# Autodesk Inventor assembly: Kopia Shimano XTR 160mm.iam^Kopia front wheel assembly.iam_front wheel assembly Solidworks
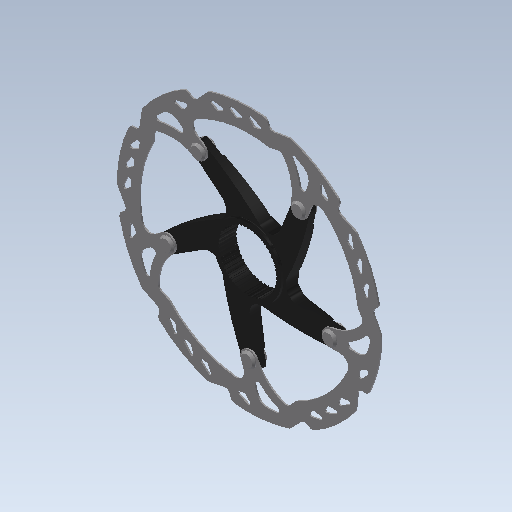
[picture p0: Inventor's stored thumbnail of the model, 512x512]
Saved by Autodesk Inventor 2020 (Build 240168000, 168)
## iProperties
Created: 2017-09
Part Number: Kopia Shimano XTR 160mm.iam^Kopia front wheel assembly.iam_front wheel assembly Solidworks
Material: Ogólny
Document SubType Name: Assembly
Designer: Tomasz
Sending System: SolidWorks 2017
Last Author: Tomasz
Last Saved: 2017-09-11
Author: Tomasz
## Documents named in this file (4)
- C:\Users\bruno\Documents\1-Cours-2020-21\1STI2D-2020-21\IT\6. Antivol\Inventor-Antivol\INVENTOR 2018_Steel Hardtail B+\Kopia Shimano XTR 160mm.iam^Kopia front wheel assembly.iam_front wheel assembly Solidworks.iam
- C:\Users\bruno\Documents\1-Cours-2020-21\1STI2D-2020-21\IT\6. Antivol\Inventor-Antivol\INVENTOR 2018_Steel Hardtail B+\Kopia disk rotor.ipt^Kopia Shimano XTR 160mm.iam_Kopia front wheel assembly.iam_front wheel assembly.ipt
- C:\Users\bruno\Documents\1-Cours-2020-21\1STI2D-2020-21\IT\6. Antivol\Inventor-Antivol\INVENTOR 2018_Steel Hardtail B+\Kopia rotor spider.ipt^Kopia Shimano XTR 160mm.iam_Kopia front wheel assembly.iam_front wheel assembly.ipt
- C:\Users\bruno\Documents\1-Cours-2020-21\1STI2D-2020-21\IT\6. Antivol\Inventor-Antivol\INVENTOR 2018_Steel Hardtail B+\Kopia nit.ipt^Kopia Shimano XTR 160mm.iam_Kopia front wheel assembly.iam_front wheel assembly.ipt
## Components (7 placed, 3 different names)
1. Kopia disk rotor.ipt^Kopia Shimano XTR 160mm.iam_Kopia front wheel assembly.iam_front wheel assembly Solidworks:1
2. Kopia rotor spider.ipt^Kopia Shimano XTR 160mm.iam_Kopia front wheel assembly.iam_front wheel assembly Solidworks:1
3. Kopia nit.ipt^Kopia Shimano XTR 160mm.iam_Kopia front wheel assembly.iam_front wheel assembly Solidworks:1
4. Kopia nit.ipt^Kopia Shimano XTR 160mm.iam_Kopia front wheel assembly.iam_front wheel assembly Solidworks:2
5. Kopia nit.ipt^Kopia Shimano XTR 160mm.iam_Kopia front wheel assembly.iam_front wheel assembly Solidworks:3
6. Kopia nit.ipt^Kopia Shimano XTR 160mm.iam_Kopia front wheel assembly.iam_front wheel assembly Solidworks:4
7. Kopia nit.ipt^Kopia Shimano XTR 160mm.iam_Kopia front wheel assembly.iam_front wheel assembly Solidworks:5
